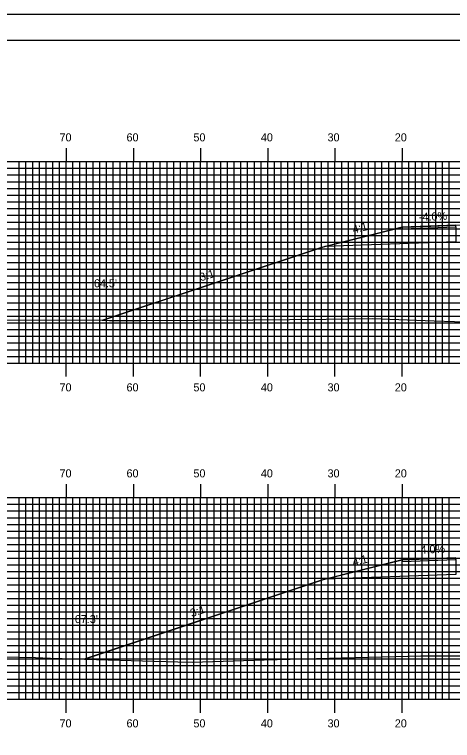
# Model space of a CAD drawing. Extents: x 1762578 to 1762921, y 442591 to 442811.
# Drawn here: x 1762666.1 to 1762731.3, y 442702.5 to 442810.5 of the extents above; entities that cross this region are included whole.
import ezdxf

# ---------------------------------------------------------------- set-up
doc = ezdxf.new("R2010")
doc.units = 0
for name, color, linetype in [('ANNOTATION', 7, 'Continuous'), ('BORDER', 7, 'Continuous'), ('D_Roadway_Centerline', 7, 'Continuous'), ('D_Roadway_Edge_Shoulder', 7, 'Continuous'), ('D_Roadway_SlopeLines', 7, 'Continuous'), ('D_Roadway_SubGrade', 7, 'Continuous'), ('D_Text_Standard', 7, 'Continuous'), ('H_V ANNOTATION', 7, 'Continuous'), ('MAJOR', 7, 'Continuous'), ('MINOR', 7, 'Continuous'), ('PLOT BOUNDARY', 7, 'Continuous'), ('S_Roadway_Centerline', 7, 'Continuous')]:
    doc.layers.add(name, color=color, linetype=linetype)

msp = doc.modelspace()

# ---------------------------------------------------------------- linework, layer by layer
at = {"layer": 'BORDER'}
msp.add_lwpolyline([(1762594.18, 442596.67), (1762914.18, 442596.67), (1762914.18, 442806.67), (1762594.18, 442806.67)], close=True, dxfattribs=at)
at = {"layer": 'D_Roadway_Centerline'}
for points in [[(1762679.23, 442765.05), (1762679.24, 442765.05), (1762683.25, 442766.39), (1762711.78, 442775.9), (1762712.06, 442775.97), (1762712.25, 442776.02), (1762712.25, 442776.02), (1762719.64, 442777.87), (1762723.78, 442778.9), (1762725.57, 442778.97), (1762731.78, 442779.22), (1762741.55, 442779.57), (1762743.78, 442779.66), (1762743.78, 442779.66), (1762749.62, 442779.87), (1762755.78, 442780.09), (1762755.78, 442780.09), (1762763.78, 442779.77), (1762763.78, 442779.77), (1762772.96, 442777.47), (1762773.95, 442777.22), (1762775.78, 442776.77), (1762775.79, 442776.76), (1762797.43, 442769.55)], [(1762676.46, 442714.63), (1762676.47, 442714.63), (1762693.61, 442720.35), (1762711.76, 442726.4), (1762711.78, 442726.4), (1762712.1, 442726.48), (1762712.25, 442726.52), (1762723.78, 442729.4), (1762724.97, 442729.45), (1762731.78, 442729.72)]]:
    msp.add_lwpolyline(points, dxfattribs=at)
at = {"layer": 'D_Roadway_Edge_Shoulder'}
for points in [[(1762731.78, 442779.22), (1762723.78, 442778.9), (1762723.78, 442778.65), (1762731.78, 442778.97)], [(1762731.78, 442729.72), (1762723.78, 442729.4), (1762723.78, 442729.15), (1762731.78, 442729.47)]]:
    msp.add_lwpolyline(points, close=True, dxfattribs=at)
at = {"layer": 'D_Roadway_SlopeLines'}
for points in [[(1762723.78, 442778.9), (1762711.78, 442775.9), (1762679.23, 442765.05)], [(1762723.78, 442729.4), (1762711.78, 442726.4), (1762676.46, 442714.63)]]:
    msp.add_lwpolyline(points, dxfattribs=at)
at = {"layer": 'D_Roadway_SubGrade'}
for points in [[(1762723.78, 442778.65), (1762731.78, 442778.97), (1762731.78, 442778.56), (1762731.78, 442776.72), (1762712.25, 442776.02), (1762723.78, 442778.9)], [(1762723.78, 442729.15), (1762731.78, 442729.47), (1762731.78, 442729.06), (1762731.78, 442727.22), (1762712.25, 442726.52), (1762723.78, 442729.4)]]:
    msp.add_lwpolyline(points, close=True, dxfattribs=at)
at = {"layer": 'MAJOR'}
for p, q in [((1762673.78, 442790.67), (1762673.78, 442788.67)), ((1762683.78, 442790.67), (1762683.78, 442788.67)), ((1762693.78, 442790.67), (1762693.78, 442788.67)), ((1762703.78, 442790.67), (1762703.78, 442788.67)), ((1762713.78, 442790.67), (1762713.78, 442788.67)), ((1762723.78, 442790.67), (1762723.78, 442788.67)), ((1762603.78, 442788.67), (1762883.78, 442788.67)), ((1762603.78, 442788.67), (1762883.78, 442788.67)), ((1762673.78, 442758.67), (1762673.78, 442788.67)), ((1762683.78, 442758.67), (1762683.78, 442788.67)), ((1762693.78, 442758.67), (1762693.78, 442788.67)), ((1762703.78, 442758.67), (1762703.78, 442788.67)), ((1762713.78, 442758.67), (1762713.78, 442788.67)), ((1762723.78, 442758.67), (1762723.78, 442788.67)), ((1762603.78, 442783.67), (1762883.78, 442783.67)), ((1762603.78, 442778.67), (1762883.78, 442778.67)), ((1762603.78, 442773.67), (1762883.78, 442773.67)), ((1762603.78, 442768.67), (1762883.78, 442768.67)), ((1762603.78, 442763.67), (1762883.78, 442763.67)), ((1762603.78, 442758.67), (1762883.78, 442758.67)), ((1762603.78, 442758.67), (1762883.78, 442758.67)), ((1762673.78, 442756.66), (1762673.78, 442758.67)), ((1762683.78, 442756.66), (1762683.78, 442758.67)), ((1762693.78, 442756.66), (1762693.78, 442758.67)), ((1762703.78, 442756.66), (1762703.78, 442758.67)), ((1762713.78, 442756.66), (1762713.78, 442758.67)), ((1762723.78, 442756.66), (1762723.78, 442758.67)), ((1762673.78, 442740.67), (1762673.78, 442738.67)), ((1762683.78, 442740.67), (1762683.78, 442738.67)), ((1762693.78, 442740.67), (1762693.78, 442738.67)), ((1762703.78, 442740.67), (1762703.78, 442738.67)), ((1762713.78, 442740.67), (1762713.78, 442738.67)), ((1762723.78, 442740.67), (1762723.78, 442738.67)), ((1762603.78, 442738.67), (1762883.78, 442738.67)), ((1762603.78, 442738.67), (1762883.78, 442738.67)), ((1762673.78, 442708.67), (1762673.78, 442738.67)), ((1762683.78, 442708.67), (1762683.78, 442738.67)), ((1762693.78, 442708.67), (1762693.78, 442738.67)), ((1762703.78, 442708.67), (1762703.78, 442738.67)), ((1762713.78, 442708.67), (1762713.78, 442738.67)), ((1762723.78, 442708.67), (1762723.78, 442738.67)), ((1762603.78, 442733.67), (1762883.78, 442733.67)), ((1762603.78, 442728.67), (1762883.78, 442728.67)), ((1762603.78, 442723.67), (1762883.78, 442723.67)), ((1762603.78, 442718.67), (1762883.78, 442718.67)), ((1762603.78, 442713.67), (1762883.78, 442713.67)), ((1762603.78, 442708.67), (1762883.78, 442708.67)), ((1762603.78, 442708.67), (1762883.78, 442708.67)), ((1762673.78, 442706.66), (1762673.78, 442708.67)), ((1762683.78, 442706.66), (1762683.78, 442708.67)), ((1762693.78, 442706.66), (1762693.78, 442708.67)), ((1762703.78, 442706.66), (1762703.78, 442708.67)), ((1762713.78, 442706.66), (1762713.78, 442708.67)), ((1762723.78, 442706.66), (1762723.78, 442708.67))]:
    msp.add_line(p, q, dxfattribs=at)
at = {"layer": 'MINOR'}
for p, q in [((1762666.78, 442758.67), (1762666.78, 442788.67)), ((1762667.78, 442758.67), (1762667.78, 442788.67)), ((1762668.78, 442758.67), (1762668.78, 442788.67)), ((1762669.78, 442758.67), (1762669.78, 442788.67)), ((1762670.78, 442758.67), (1762670.78, 442788.67)), ((1762671.78, 442758.67), (1762671.78, 442788.67)), ((1762672.78, 442758.67), (1762672.78, 442788.67)), ((1762674.78, 442758.67), (1762674.78, 442788.67)), ((1762675.78, 442758.67), (1762675.78, 442788.67)), ((1762676.78, 442758.67), (1762676.78, 442788.67)), ((1762677.78, 442758.67), (1762677.78, 442788.67)), ((1762678.78, 442758.67), (1762678.78, 442788.67)), ((1762679.78, 442758.67), (1762679.78, 442788.67)), ((1762680.78, 442758.67), (1762680.78, 442788.67)), ((1762681.78, 442758.67), (1762681.78, 442788.67)), ((1762682.78, 442758.67), (1762682.78, 442788.67)), ((1762684.78, 442758.67), (1762684.78, 442788.67)), ((1762685.78, 442758.67), (1762685.78, 442788.67)), ((1762686.78, 442758.67), (1762686.78, 442788.67)), ((1762687.78, 442758.67), (1762687.78, 442788.67)), ((1762688.78, 442758.67), (1762688.78, 442788.67)), ((1762689.78, 442758.67), (1762689.78, 442788.67)), ((1762690.78, 442758.67), (1762690.78, 442788.67)), ((1762691.78, 442758.67), (1762691.78, 442788.67)), ((1762692.78, 442758.67), (1762692.78, 442788.67)), ((1762694.78, 442758.67), (1762694.78, 442788.67)), ((1762695.78, 442758.67), (1762695.78, 442788.67)), ((1762696.78, 442758.67), (1762696.78, 442788.67)), ((1762697.78, 442758.67), (1762697.78, 442788.67)), ((1762698.78, 442758.67), (1762698.78, 442788.67)), ((1762699.78, 442758.67), (1762699.78, 442788.67)), ((1762700.78, 442758.67), (1762700.78, 442788.67)), ((1762701.78, 442758.67), (1762701.78, 442788.67)), ((1762702.78, 442758.67), (1762702.78, 442788.67)), ((1762704.78, 442758.67), (1762704.78, 442788.67)), ((1762705.78, 442758.67), (1762705.78, 442788.67)), ((1762706.78, 442758.67), (1762706.78, 442788.67)), ((1762707.78, 442758.67), (1762707.78, 442788.67)), ((1762708.78, 442758.67), (1762708.78, 442788.67)), ((1762709.78, 442758.67), (1762709.78, 442788.67)), ((1762710.78, 442758.67), (1762710.78, 442788.67)), ((1762711.78, 442758.67), (1762711.78, 442788.67)), ((1762712.78, 442758.67), (1762712.78, 442788.67)), ((1762714.78, 442758.67), (1762714.78, 442788.67)), ((1762715.78, 442758.67), (1762715.78, 442788.67)), ((1762716.78, 442758.67), (1762716.78, 442788.67)), ((1762717.78, 442758.67), (1762717.78, 442788.67)), ((1762718.78, 442758.67), (1762718.78, 442788.67)), ((1762719.78, 442758.67), (1762719.78, 442788.67)), ((1762720.78, 442758.67), (1762720.78, 442788.67)), ((1762721.78, 442758.67), (1762721.78, 442788.67)), ((1762722.78, 442758.67), (1762722.78, 442788.67)), ((1762724.78, 442758.67), (1762724.78, 442788.67)), ((1762725.78, 442758.67), (1762725.78, 442788.67)), ((1762726.78, 442758.67), (1762726.78, 442788.67)), ((1762727.78, 442758.67), (1762727.78, 442788.67)), ((1762728.78, 442758.67), (1762728.78, 442788.67)), ((1762729.78, 442758.67), (1762729.78, 442788.67)), ((1762730.78, 442758.67), (1762730.78, 442788.67)), ((1762603.78, 442787.67), (1762883.78, 442787.67)), ((1762603.78, 442786.67), (1762883.78, 442786.67)), ((1762603.78, 442785.67), (1762883.78, 442785.67)), ((1762603.78, 442784.67), (1762883.78, 442784.67)), ((1762603.78, 442782.67), (1762883.78, 442782.67)), ((1762603.78, 442781.67), (1762883.78, 442781.67)), ((1762603.78, 442780.67), (1762883.78, 442780.67)), ((1762603.78, 442779.67), (1762883.78, 442779.67)), ((1762603.78, 442777.67), (1762883.78, 442777.67)), ((1762603.78, 442776.67), (1762883.78, 442776.67)), ((1762603.78, 442775.67), (1762883.78, 442775.67)), ((1762603.78, 442774.67), (1762883.78, 442774.67)), ((1762603.78, 442772.67), (1762883.78, 442772.67)), ((1762603.78, 442771.67), (1762883.78, 442771.67)), ((1762603.78, 442770.67), (1762883.78, 442770.67)), ((1762603.78, 442769.67), (1762883.78, 442769.67)), ((1762603.78, 442767.67), (1762883.78, 442767.67)), ((1762603.78, 442766.67), (1762883.78, 442766.67)), ((1762603.78, 442765.67), (1762883.78, 442765.67)), ((1762603.78, 442764.67), (1762883.78, 442764.67)), ((1762603.78, 442762.67), (1762883.78, 442762.67)), ((1762603.78, 442761.67), (1762883.78, 442761.67)), ((1762603.78, 442760.67), (1762883.78, 442760.67)), ((1762603.78, 442759.67), (1762883.78, 442759.67)), ((1762666.78, 442708.67), (1762666.78, 442738.67)), ((1762667.78, 442708.67), (1762667.78, 442738.67)), ((1762668.78, 442708.67), (1762668.78, 442738.67)), ((1762669.78, 442708.67), (1762669.78, 442738.67)), ((1762670.78, 442708.67), (1762670.78, 442738.67)), ((1762671.78, 442708.67), (1762671.78, 442738.67)), ((1762672.78, 442708.67), (1762672.78, 442738.67)), ((1762674.78, 442708.67), (1762674.78, 442738.67)), ((1762675.78, 442708.67), (1762675.78, 442738.67)), ((1762676.78, 442708.67), (1762676.78, 442738.67)), ((1762677.78, 442708.67), (1762677.78, 442738.67)), ((1762678.78, 442708.67), (1762678.78, 442738.67)), ((1762679.78, 442708.67), (1762679.78, 442738.67)), ((1762680.78, 442708.67), (1762680.78, 442738.67)), ((1762681.78, 442708.67), (1762681.78, 442738.67)), ((1762682.78, 442708.67), (1762682.78, 442738.67)), ((1762684.78, 442708.67), (1762684.78, 442738.67)), ((1762685.78, 442708.67), (1762685.78, 442738.67)), ((1762686.78, 442708.67), (1762686.78, 442738.67)), ((1762687.78, 442708.67), (1762687.78, 442738.67)), ((1762688.78, 442708.67), (1762688.78, 442738.67)), ((1762689.78, 442708.67), (1762689.78, 442738.67)), ((1762690.78, 442708.67), (1762690.78, 442738.67)), ((1762691.78, 442708.67), (1762691.78, 442738.67)), ((1762692.78, 442708.67), (1762692.78, 442738.67)), ((1762694.78, 442708.67), (1762694.78, 442738.67)), ((1762695.78, 442708.67), (1762695.78, 442738.67)), ((1762696.78, 442708.67), (1762696.78, 442738.67)), ((1762697.78, 442708.67), (1762697.78, 442738.67)), ((1762698.78, 442708.67), (1762698.78, 442738.67)), ((1762699.78, 442708.67), (1762699.78, 442738.67)), ((1762700.78, 442708.67), (1762700.78, 442738.67)), ((1762701.78, 442708.67), (1762701.78, 442738.67)), ((1762702.78, 442708.67), (1762702.78, 442738.67)), ((1762704.78, 442708.67), (1762704.78, 442738.67)), ((1762705.78, 442708.67), (1762705.78, 442738.67)), ((1762706.78, 442708.67), (1762706.78, 442738.67)), ((1762707.78, 442708.67), (1762707.78, 442738.67)), ((1762708.78, 442708.67), (1762708.78, 442738.67)), ((1762709.78, 442708.67), (1762709.78, 442738.67)), ((1762710.78, 442708.67), (1762710.78, 442738.67)), ((1762711.78, 442708.67), (1762711.78, 442738.67)), ((1762712.78, 442708.67), (1762712.78, 442738.67)), ((1762714.78, 442708.67), (1762714.78, 442738.67)), ((1762715.78, 442708.67), (1762715.78, 442738.67)), ((1762716.78, 442708.67), (1762716.78, 442738.67)), ((1762717.78, 442708.67), (1762717.78, 442738.67)), ((1762718.78, 442708.67), (1762718.78, 442738.67)), ((1762719.78, 442708.67), (1762719.78, 442738.67)), ((1762720.78, 442708.67), (1762720.78, 442738.67)), ((1762721.78, 442708.67), (1762721.78, 442738.67)), ((1762722.78, 442708.67), (1762722.78, 442738.67)), ((1762724.78, 442708.67), (1762724.78, 442738.67)), ((1762725.78, 442708.67), (1762725.78, 442738.67)), ((1762726.78, 442708.67), (1762726.78, 442738.67)), ((1762727.78, 442708.67), (1762727.78, 442738.67)), ((1762728.78, 442708.67), (1762728.78, 442738.67)), ((1762729.78, 442708.67), (1762729.78, 442738.67)), ((1762730.78, 442708.67), (1762730.78, 442738.67)), ((1762603.78, 442737.67), (1762883.78, 442737.67)), ((1762603.78, 442736.67), (1762883.78, 442736.67)), ((1762603.78, 442735.67), (1762883.78, 442735.67)), ((1762603.78, 442734.67), (1762883.78, 442734.67)), ((1762603.78, 442732.67), (1762883.78, 442732.67)), ((1762603.78, 442731.67), (1762883.78, 442731.67)), ((1762603.78, 442730.67), (1762883.78, 442730.67)), ((1762603.78, 442729.67), (1762883.78, 442729.67)), ((1762603.78, 442727.67), (1762883.78, 442727.67)), ((1762603.78, 442726.67), (1762883.78, 442726.67)), ((1762603.78, 442725.67), (1762883.78, 442725.67)), ((1762603.78, 442724.67), (1762883.78, 442724.67)), ((1762603.78, 442722.67), (1762883.78, 442722.67)), ((1762603.78, 442721.67), (1762883.78, 442721.67)), ((1762603.78, 442720.67), (1762883.78, 442720.67)), ((1762603.78, 442719.67), (1762883.78, 442719.67)), ((1762603.78, 442717.67), (1762883.78, 442717.67)), ((1762603.78, 442716.67), (1762883.78, 442716.67)), ((1762603.78, 442715.67), (1762883.78, 442715.67)), ((1762603.78, 442714.67), (1762883.78, 442714.67)), ((1762603.78, 442712.67), (1762883.78, 442712.67)), ((1762603.78, 442711.67), (1762883.78, 442711.67)), ((1762603.78, 442710.67), (1762883.78, 442710.67)), ((1762603.78, 442709.67), (1762883.78, 442709.67))]:
    msp.add_line(p, q, dxfattribs=at)
at = {"layer": 'PLOT BOUNDARY'}
msp.add_lwpolyline([(1762577.99, 442590.55), (1762917.99, 442590.55), (1762917.99, 442810.55), (1762577.99, 442810.55)], close=True, dxfattribs=at)
at = {"layer": 'S_Roadway_Centerline'}
for points in [[(1762655.76, 442765.13), (1762679.13, 442765.06), (1762680.21, 442765.02), (1762681.02, 442765.01), (1762684.95, 442765.03), (1762701.53, 442765.1), (1762712.45, 442765.21), (1762719.32, 442765.32), (1762728.54, 442764.98), (1762737.61, 442764.69), (1762739.67, 442764.8), (1762743.43, 442765.07), (1762751.81, 442765.72), (1762755.81, 442765.92), (1762768.16, 442767.1), (1762774.19, 442767.68), (1762779.34, 442768.07), (1762793.46, 442769.52), (1762808.18, 442769.62)], [(1762603.78, 442715.93), (1762615, 442715.29), (1762621.56, 442715.29), (1762639.34, 442715.45), (1762647.68, 442715.27), (1762661.87, 442715), (1762669.22, 442714.86), (1762671.41, 442714.79), (1762686.85, 442714.31), (1762690.37, 442714.22), (1762692.53, 442714.2), (1762703.22, 442714.51), (1762726.59, 442715.11), (1762729.34, 442715.14), (1762733.92, 442715.11), (1762750.45, 442715.09), (1762756.11, 442715.29), (1762766.02, 442715.74), (1762774.05, 442716.61), (1762784.72, 442717.56), (1762788.78, 442717.85), (1762798.29, 442718.48), (1762804.53, 442719), (1762810.77, 442719.38)]]:
    msp.add_lwpolyline(points, dxfattribs=at)

# ---------------------------------------------------------------- texts
at = {"layer": 'ANNOTATION'}
for s, rotation, p in [('-4.0%', 2.2908, (1762726.3, 442779.81)), ('4:1', 14.0396, (1762716.55, 442777.96)), ('3:1', 18.4357, (1762693.85, 442770.83)), ('-4.0%', 2.2904, (1762726.01, 442730.29)), ('4:1', 14.0405, (1762716.55, 442728.46)), ('3:1', 18.4359, (1762692.46, 442720.87))]:
    msp.add_text(s, height=1.2, rotation=rotation, dxfattribs=at).set_placement(p)
at = {"layer": 'D_Text_Standard'}
for s, p in [("64.5'", (1762677.9, 442769.96)), ("67.3'", (1762675.05, 442719.99))]:
    msp.add_text(s, height=1.2, dxfattribs=at).set_placement(p)
at = {"layer": 'H_V ANNOTATION'}
for s, p in [('70', (1762672.78, 442791.67)), ('60', (1762682.75, 442791.67)), ('50', (1762692.71, 442791.67)), ('40', (1762702.75, 442791.67)), ('30', (1762712.68, 442791.67)), ('20', (1762722.69, 442791.67)), ('70', (1762672.78, 442754.47)), ('60', (1762682.75, 442754.47)), ('50', (1762692.71, 442754.47)), ('40', (1762702.75, 442754.47)), ('30', (1762712.68, 442754.47)), ('20', (1762722.69, 442754.47)), ('70', (1762672.78, 442741.67)), ('60', (1762682.75, 442741.67)), ('50', (1762692.71, 442741.67)), ('40', (1762702.75, 442741.67)), ('30', (1762712.68, 442741.67)), ('20', (1762722.69, 442741.67)), ('70', (1762672.78, 442704.47)), ('60', (1762682.75, 442704.47)), ('50', (1762692.71, 442704.47)), ('40', (1762702.75, 442704.47)), ('30', (1762712.68, 442704.47)), ('20', (1762722.69, 442704.47))]:
    msp.add_text(s, height=1.2, dxfattribs=at).set_placement(p)

doc.saveas('drawing.dxf')
